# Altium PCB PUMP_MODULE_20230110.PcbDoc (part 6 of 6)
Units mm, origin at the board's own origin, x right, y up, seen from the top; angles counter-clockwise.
Board outline 260.15 x 142.01 mm, 4 copper layers (Top Layer, Mid-Layer 1, Mid-Layer 2, Bottom Layer); 422 components, 240 nets, 1746 pads, 416 vias.
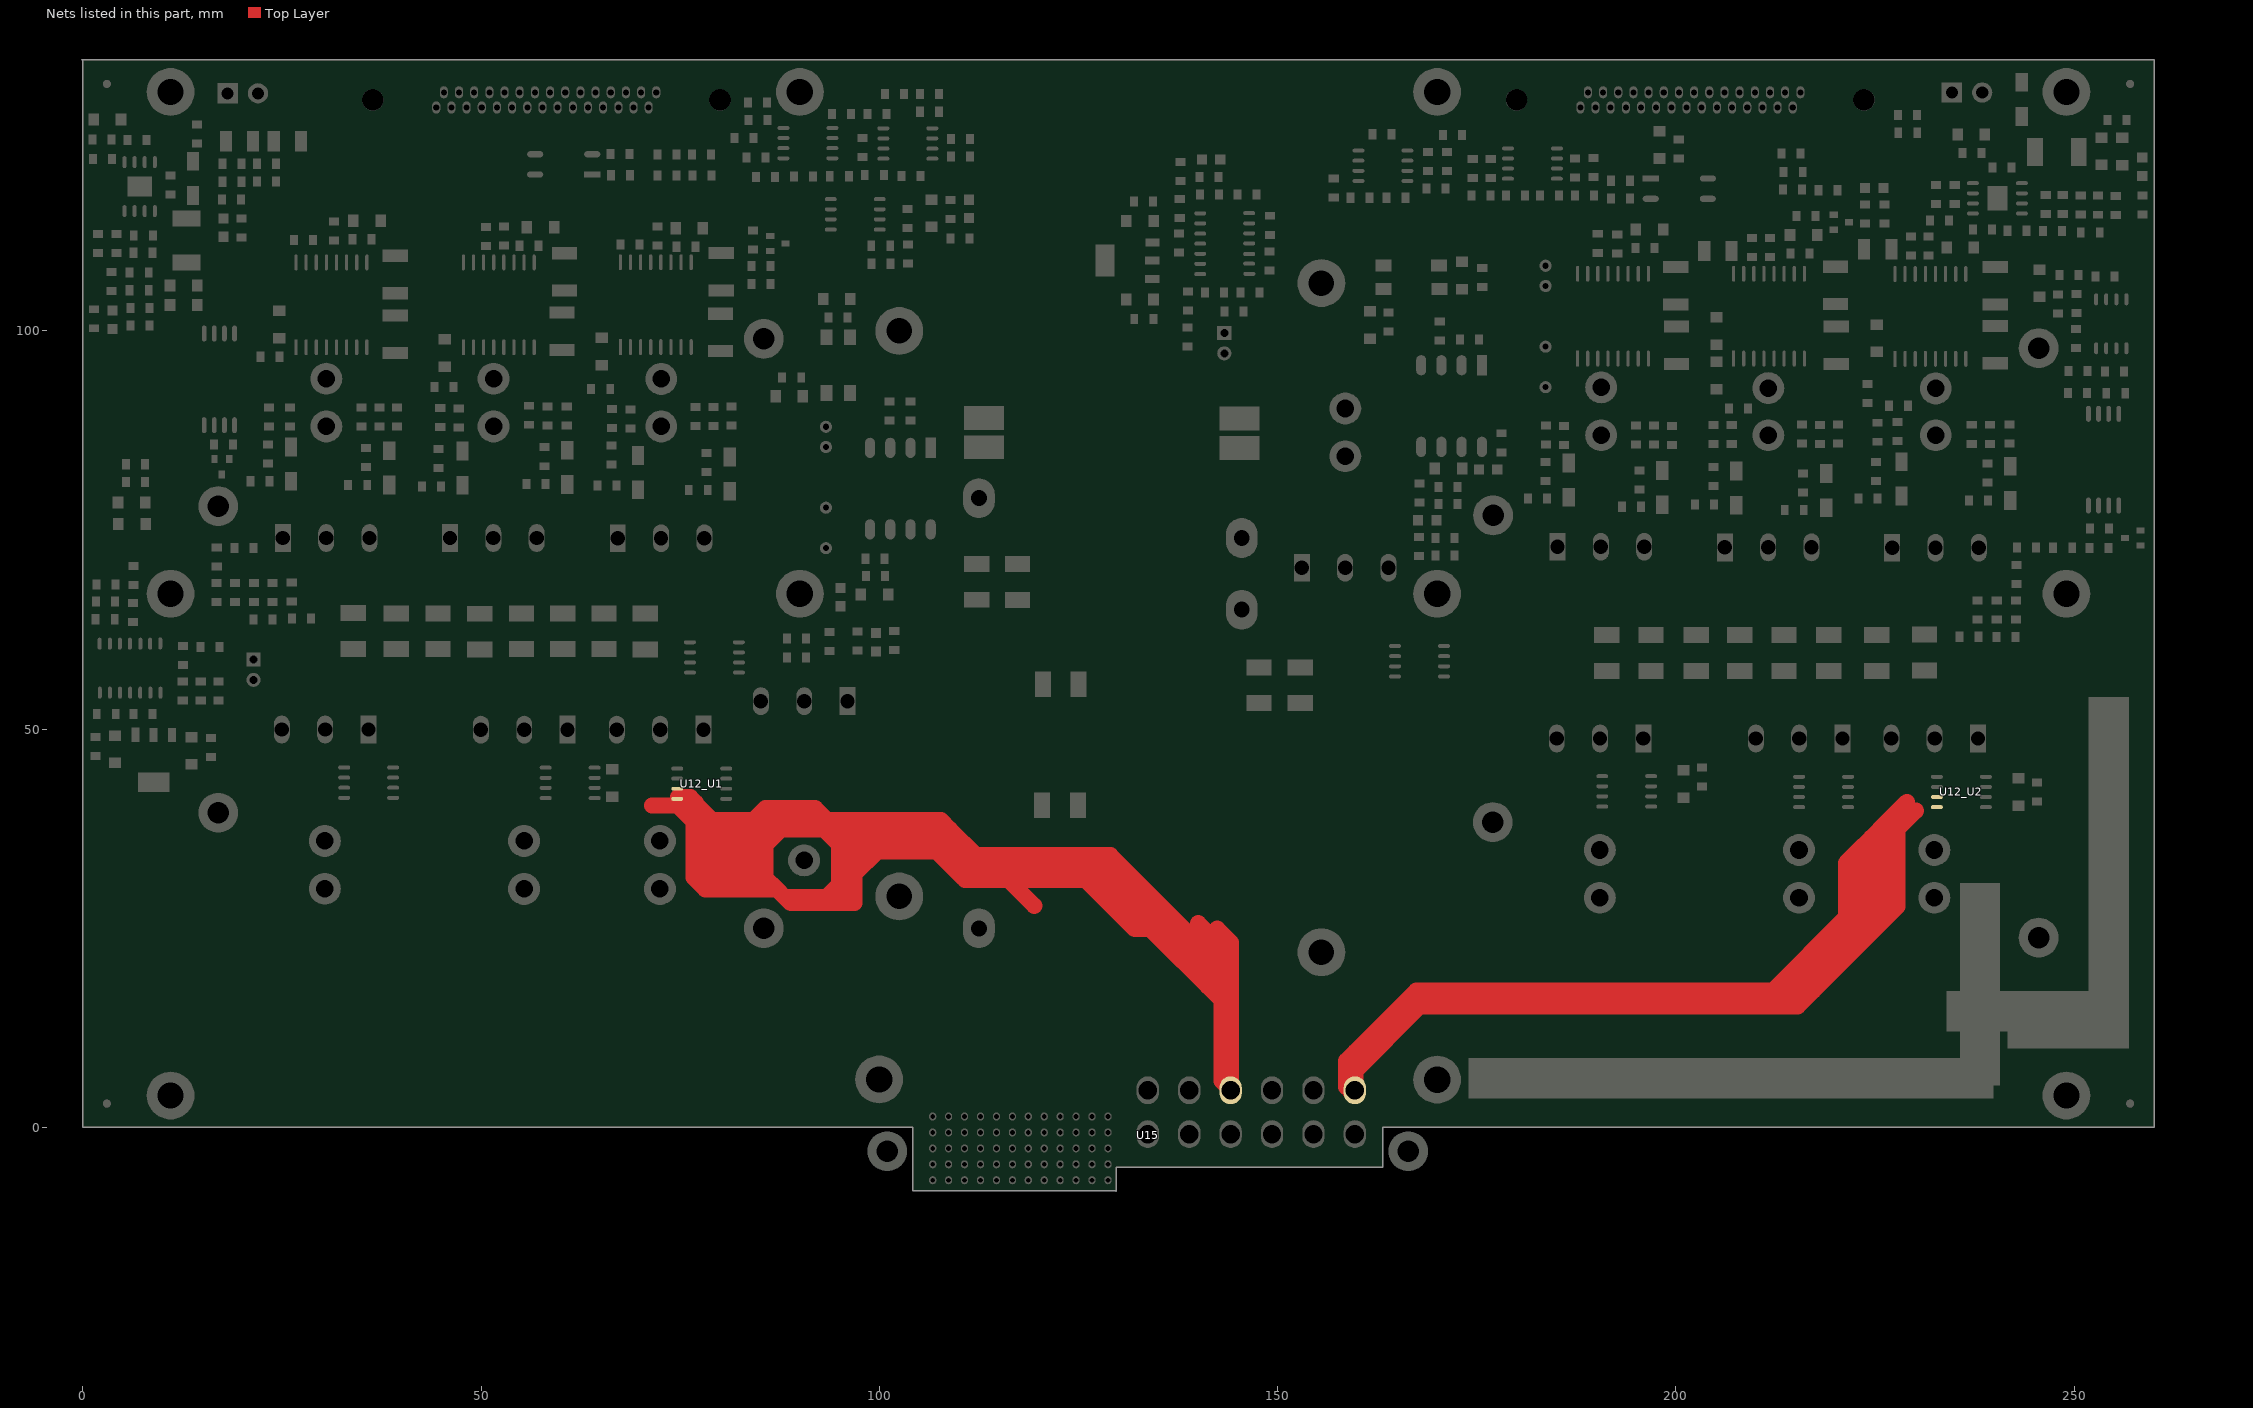
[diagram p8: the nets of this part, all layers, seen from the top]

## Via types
v1: diameter 0.762, hole 0.508, Top Layer to Bottom Layer, 208 vias
v2: diameter 2.032, hole 1.27, Top Layer to Bottom Layer, 78 vias
v3: diameter 1.27, hole 0.762, Top Layer to Bottom Layer, 61 vias
v4: diameter 1.524, hole 1.016, Top Layer to Bottom Layer, 53 vias
v5: diameter 1.27, hole 0.711, Top Layer to Bottom Layer, 16 vias

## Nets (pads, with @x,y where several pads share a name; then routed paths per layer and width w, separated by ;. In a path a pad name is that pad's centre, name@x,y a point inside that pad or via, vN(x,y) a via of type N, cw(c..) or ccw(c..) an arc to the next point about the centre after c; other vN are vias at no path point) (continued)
WW_OUT1: U12_U1.3 U12_U1.4 U15.3 | length 454.5
  Top Layer w2.032: 71.476,40.411 74.701,40.411 76.391,38.722 ; U12_U1.4@74.727,41.478 76.251,41.478 ; 76.632,38.481 77.013,38.1 ; 76.657,37.973 76.657,35.255 ; 78.232,36.881 77.013,38.1 ; 119.456,27.838 116.205,31.09 ; 126.848,34.163 128.054,32.956 ; 140.03,25.629 144.141,21.518 ; 142.418,24.943 144.141,23.219 144.141,21.518 ; 76.251,41.478 76.251,41.326 76.276,41.3 ; 76.251,41.478 76.276,41.453 ; 76.276,41.3 76.962,40.615 ; 76.276,41.3 76.276,41.453 ; 76.276,41.3 76.276,39.497 77.343,38.43 ; 76.276,41.453 76.962,40.767 76.962,40.615 ; 76.657,33.68 76.657,31.394 78.156,29.896 80.442,29.896 ; 76.657,33.68 76.657,35.255 ; 76.657,33.68 77.775,32.563 ; 76.657,35.255 77.597,34.315 84.582,34.315 85.7,35.433 ; 76.962,40.615 77.343,40.234 ; 77.013,38.1 77.343,38.43 ; 77.013,38.1 77.013,35.941 77.521,35.433 85.7,35.433 ; 77.343,38.43 77.343,39.37 ; 77.343,38.43 78.969,36.805 78.969,37.744 ; 77.343,39.37 77.343,40.234 ; 77.343,39.37 78.969,37.744 ; 77.343,40.234 79.019,38.557 84.176,38.557 ; 77.775,32.563 79.273,31.064 ; 77.775,32.563 85.115,32.563 85.7,33.147 ; 78.969,37.744 79.273,37.44 87.706,37.44 ; 79.273,31.064 80.442,29.896 ; 79.273,31.064 79.35,31.14 85.7,31.14 ; 80.442,29.896 84.607,29.896 ; 84.176,38.557 85.7,40.081 90.881,40.081 ; 84.176,38.557 92.405,38.557 ; 84.607,29.896 87.147,29.896 ; 84.607,29.896 85.776,31.064 85.7,31.14 ; 85.7,31.14 85.7,31.344 ; 85.7,31.344 87.147,29.896 ; 85.7,31.344 85.7,33.147 ; 85.7,33.147 85.7,35.433 ; 85.7,35.433 87.706,37.44 ; 87.147,29.896 88.151,28.892 ; 87.706,37.44 93.015,37.44 ; 88.151,28.892 88.875,28.169 95.275,28.169 ; 88.151,28.892 93.332,28.892 94.945,30.505 ; 90.881,40.081 91.948,40.081 93.472,38.557 ; 90.881,40.081 92.405,38.557 ; 92.405,38.557 93.472,38.557 ; 93.015,37.44 94.945,35.509 ; 93.015,37.44 108.864,37.44 ; 93.472,38.557 107.747,38.557 108.864,37.44 ; 94.945,30.505 94.945,35.509 ; 94.945,30.505 94.945,28.499 95.275,28.169 ; 94.945,35.509 99.644,35.509 ; 94.945,35.509 95.771,34.684 97.511,34.684 ; 95.275,28.169 96.876,28.169 96.876,31.775 ; 96.876,31.775 96.876,32.741 ; 96.876,31.775 99.784,34.684 ; 96.876,32.741 96.876,34.049 97.511,34.684 ; 96.876,32.741 98.819,34.684 ; 97.511,34.684 98.819,34.684 ; 98.819,34.684 99.784,34.684 ; 98.819,34.684 99.644,35.509 ; 99.644,35.509 100.571,35.509 101.397,34.684 ; 99.644,35.509 99.746,35.611 106.248,35.611 ; 99.784,34.684 101.397,34.684 ; 101.397,34.684 107.175,34.684 ; 106.248,35.611 108.458,35.611 111.303,32.766 126.162,32.766 ; 106.248,35.611 107.175,34.684 ; 107.175,34.684 110.49,31.369 ; 108.864,37.44 112.141,34.163 124.765,34.163 ; 110.49,31.369 110.769,31.09 116.205,31.09 ; 110.49,31.369 125.603,31.369 125.882,31.09 ; 116.205,31.09 125.882,31.09 ; 124.765,34.163 129.007,34.163 144.141,19.028 ; 124.765,34.163 126.162,32.766 ; 125.882,31.09 132.055,24.917 134.01,24.917 135.077,23.851 ; 126.162,32.766 135.077,23.851 ; 126.162,32.766 127.864,32.766 128.054,32.956 ; 128.054,32.956 136.601,24.409 ; 135.077,23.851 136.042,23.851 136.601,24.409 ; 135.077,23.851 141.224,17.704 ; 136.601,24.409 144.141,16.869 ; 141.224,17.704 142.977,15.951 ; 141.224,17.704 142.977,17.704 ; 142.977,7.518 142.977,15.951 ; 142.977,7.518 U15.3@144.141,6.354 ; 142.977,7.518 142.977,5.827 144.141,4.663 U15.3@144.141,6.354 ; 142.977,15.951 142.977,17.704 ; 142.977,17.704 144.141,16.539 ; U15.3@144.141,6.354 144.141,16.539 ; 144.141,16.539 144.141,16.869 ; 144.141,16.869 144.141,19.028 ; 144.141,19.028 144.141,21.518
WW_OUT2: U12_U2.3 U12_U2.4 U15.6 | length 236.1
  Top Layer w2.032: 229.006,40.869 226.416,38.278 ; 230.124,39.751 227.813,37.44 227.813,27.737 217.246,17.17 ; 159.741,7.087 159.741,9.5 ; 159.741,7.087 159.741,4.663 159.04,4.663 158.623,5.08 158.623,8.382 159.741,9.5 ; 159.741,7.087 167.869,15.215 215.29,15.215 217.246,17.17 ; 159.741,9.5 167.411,17.17 212.141,17.17 ; 212.141,17.17 214.63,17.17 ; 212.141,17.17 221.336,26.365 ; 214.63,17.17 217.246,17.17 ; 214.63,17.17 226.416,28.956 226.416,38.278 ; 221.336,26.365 221.336,33.198 222.847,34.709 ; 221.336,26.365 222.847,27.877 ; 222.847,27.877 222.847,34.709 ; 222.847,27.877 224.511,29.54 224.511,36.373 ; 222.847,34.709 224.511,36.373 ; 224.511,36.373 226.416,38.278
pads on no net: C4.0 P4_U1. P4_U1.9 P4_U1.10 P4_U1.22 P4_U1.24 P4_U1.25 P4_U2. P4_U2.9 P4_U2.10 P4_U2.22 P4_U2.24 P4_U2.25 Q1_U1. Q1_U2. Q2_U1. Q2_U2. Q3_U1. Q3_U2. Q4_U1. Q4_U2. Q5_U1. Q5_U2. Q7_U1. Q7_U2. Q8_U1. Q8_U2. U1_U1.5 U1_U1.6 U1_U1.7 U1_U2.5 U1_U2.6 U1_U2.7 U2_U1.4 U2_U2.4 U5_U1.6 U5_U2.6 U6_U1.4 U6_U1.5 U6_U1.9 U6_U1.10 U6_U1.16 U6_U2.4 U6_U2.5 U6_U2.9 U6_U2.10 U6_U2.16 U7_U1.6 U7_U2.6 U9_U1.4 U9_U1.5 U9_U1.9 U9_U1.10 U9_U1.16 U9_U2.4 U9_U2.5 U9_U2.9 U9_U2.10 U9_U2.16 U10_U1.6 U10_U2.6 U11_U1.4 U11_U1.5 U11_U1.9 U11_U1.10 U11_U1.16 U11_U2.4 U11_U2.5 U11_U2.9 U11_U2.10 U11_U2.16 U12_U1.6 U12_U2.6 U15. U15.8 U15.9 U15.10 U15.11 U15.A1 U15.A2 U15.A3 U15.A4 U15.A5 U15.A6 U15.A7 U15.A8 U15.A9 U15.A10 U15.A11 U15.A12 U15.B1 U15.B2 U15.B3 U15.B4 U15.B5 U15.B6 U15.B7 U15.B8 U15.B9 U15.B10 U15.B11 U15.B12 U15.C1 U15.C2 U15.C3 U15.C4 U15.C5 U15.C6 U15.C7 U15.C8 U15.C9 U15.C10 U15.C11 U15.C12 U15.D1 U15.D2 U15.D3 U15.D4 U15.D5 U15.D6 U15.D7 U15.D8 U15.D9 U15.D10 U15.D11 U15.D12 U15.E1 U15.E2 U15.E3 U15.E4 U15.E5 U15.E6 U15.E7 U15.E8 U15.E9 U15.E10 U15.E11 U15.E12 U17_U1.1 U17_U1.4 U17_U1.6 U17_U2.1 U17_U2.4 U17_U2.6

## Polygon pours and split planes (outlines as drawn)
AGND_U2 on Bottom Layer "Top Layer-No Net" (solid, remove dead copper, pour order 18): 128.448,133.985 127.61,133.147 127.61,101.422 146.558,101.422 150.012,104.877 150.012,107.188 150.012,114.859 149.098,115.773 190.5,115.773 190.729,116.002 190.881,115.849 195.478,115.849 197.637,115.849 197.79,115.697 197.714,115.773 197.714,133.909 175.59,133.909 175.514,133.833 175.438,133.909 174.904,133.909 174.904,126.441 174.447,125.984 174.219,125.755 165.837,125.755 165.837,125.781 164.846,126.771 164.541,127.076 164.541,133.909 127.701,133.909 127.61,134 127.635,133.975 127.635,133.02
AGND_U1 on Bottom Layer "Top Layer-No Net" (solid, remove dead copper, pour order 13): 65.43,133.794 65.481,133.744 65.481,118.377 91.389,118.377 93.523,116.243 93.65,116.116 93.65,112.281 112.166,112.281 112.395,112.509 112.395,133.794 93.802,133.794 93.98,133.617 93.98,126.047 85.852,126.047 85.801,125.997 85.446,126.352 85.446,133.896 65.43,133.896
+5VA_U2 on Mid-Layer 2 "Top Layer-No Net" (solid, remove dead copper, pour order 17): 128.549,133.782 127.711,132.944 127.711,101.219 146.66,101.219 150.114,104.673 150.114,106.985 150.114,114.656 149.2,115.57 190.602,115.57 190.83,115.799 190.983,115.646 195.58,115.646 197.739,115.646 197.891,115.494 197.815,115.57 197.815,133.706 175.692,133.706 175.616,133.629 175.539,133.706 175.006,133.706 175.006,126.238 174.549,125.781 174.32,125.552 165.938,125.552 165.938,125.578 164.948,126.568 164.643,126.873 164.643,133.706 127.802,133.706 127.711,133.797 127.737,133.771 127.737,132.817
+5VA_U1 on Mid-Layer 2 "Top Layer-No Net" (solid, remove dead copper, pour order 12): 65.507,133.909 65.557,133.858 65.557,118.491 91.465,118.491 93.599,116.357 93.726,116.23 93.726,112.395 112.243,112.395 112.471,112.624 112.471,133.909 93.878,133.909 94.056,133.731 94.056,126.162 85.928,126.162 85.877,126.111 85.522,126.467 85.522,134.01 65.507,134.01
AGND_U2 on Top Layer "Top Layer-No Net" (solid, remove dead copper, pour order 16): 128.448,133.883 127.61,133.045 127.61,101.321 146.558,101.321 150.012,104.775 150.012,107.086 150.012,114.757 149.098,115.672 190.5,115.672 190.729,115.9 190.881,115.748 195.478,115.748 197.637,115.748 197.79,115.595 197.714,115.672 197.714,133.807 175.59,133.807 175.514,133.731 175.438,133.807 174.904,133.807 174.904,126.34 174.447,125.882 174.219,125.654 165.837,125.654 165.837,125.679 164.846,126.67 164.541,126.975 164.541,133.807 127.701,133.807 127.61,133.898 127.635,133.873 127.635,132.918
AGND_U1 on Top Layer "Top Layer-No Net" (solid, remove dead copper, pour order 11): 65.507,134.087 65.557,134.036 65.557,118.669 91.465,118.669 93.599,116.535 93.726,116.408 93.726,112.573 112.243,112.573 112.471,112.801 112.471,134.087 93.878,134.087 94.056,133.909 94.056,126.34 85.928,126.34 85.877,126.289 85.522,126.644 85.522,134.188 65.507,134.188
AGND_U2 on Mid-Layer 1 "Top Layer-No Net" (solid, remove dead copper, pour order 15): 128.448,134 127.61,133.162 127.61,101.437 146.558,101.437 150.012,104.892 150.012,107.203 150.012,114.874 149.098,115.788 190.5,115.788 190.729,116.017 190.881,115.864 195.478,115.864 197.637,115.864 197.79,115.712 197.714,115.788 197.714,133.924 175.59,133.924 175.514,133.848 175.438,133.924 174.904,133.924 174.904,126.456 174.447,125.999 174.219,125.77 165.837,125.77 165.837,125.796 164.846,126.786 164.541,127.091 164.541,133.924 127.701,133.924 127.61,134.015 127.635,133.99 127.635,133.035
AGND_U2 on Mid-Layer 1 "Top Layer-No Net" (solid, remove dead copper, pour order 14): 249.276,108.788 249.276,88.621 250.292,87.605 250.317,87.579 256.261,87.579 256.261,106.959 254.864,108.356 254.533,108.687 249.326,108.687
AGND_U1 on Mid-Layer 1 "Top Layer-No Net" (solid, remove dead copper, pour order 10): 65.456,133.909 65.507,133.858 65.507,118.491 91.415,118.491 93.548,116.357 93.675,116.23 93.675,112.395 112.192,112.395 112.42,112.624 112.42,133.909 93.828,133.909 94.005,133.731 94.005,126.162 85.877,126.162 85.827,126.111 85.471,126.467 85.471,134.01 65.456,134.01

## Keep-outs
Keep-Out Layer:
  lines w0.254: 0.023,3 ccw(c3.023,3) 3.023,0 92.475,0 92.475,2.525 104.175,2.525 104.175,0.025 104.175,-7.976 129.675,-7.976 129.675,-4.975 ; 0.025,3 0.025,130.988 cw(c3.025,130.988) 3.025,133.988 ; 3.025,134 257.023,134 ; 104.225,-8.001 129.725,-8.001 129.725,-5 ; 129.667,-4.975 163.175,-4.975 ; 129.718,-5 163.149,-5 163.175,-4.975 ; 176.113,2.525 176.175,2.464 ; 176.149,0 257.023,0 ccw(c257.023,3) 260.023,3 ; 176.175,0.025 176.175,2.525 163.175,2.525 163.175,-4.975 ; 257.023,134.01 cw(c257.023,131.01) 260.023,131.01 260.023,2.972

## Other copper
Top Layer:
  rectangle net PGND: 17.323,2.261 24.587,34.95
  rectangle net PGND: 20.625,20.371 24.587,52.019
  rectangle net PGND: 43.663,48.184 51.054,56.261
  rectangle net PGND: 64.567,48.158 68.351,56.007
  rectangle net PGND: 26.746,53.67 45.136,59.411
  rectangle net WW_OUT1: 117.5,23.876 143.942,33.198
  rectangle net VV_OUT1: 58.75,16.891 75.59,25.806
  rectangle net UU_OUT1: 36.957,2.108 90.627,13.437
  rectangle net UU_OUT1: 33.985,2.032 39.345,16.434
  rectangle net PGND: 176.911,0.406 240.894,11.633
  rectangle net PGND: 42.697,20.142 51.308,30.582
  rectangle net PGND: 174.422,3.759 178.765,10.77
  rectangle net ISO_GND_U2: 165.964,101.219 186.512,103.429
  rectangle net ISO_GND_U2: 149.225,96.266 166.472,100.33
  rectangle net ISO_GND_U2: 142.164,87.478 149.962,94.107
  rectangle net ISO_GND_U1: 42.342,114.656 46.05,123.469
  rectangle net ISO_GND_U1: 110.261,87.706 116.103,96.215
  rectangle net ISO_GND_U1: 98.628,90.322 102.159,96.241
  rectangle net ISO_GND_U1: 98.628,92.507 116.053,96.241
  rectangle net PGND: 253.416,57.404 259.004,72.796
  rectangle net ISO_+15V_U2: 197.561,105.512 204.241,110.693
  rectangle net ISO_+15V_U2: 216.891,106.172 222.936,110.922
  rectangle net NetC13_U2_1: 242.164,118.262 246.075,126.238
  rectangle net ISO_+15V_U2: 229.768,121.615 235.915,131.369
  rectangle net ISO_+15V_U2: 236.855,105.893 241.554,110.592
  rectangle net PGND: 0.762,116.434 8.763,119.659
  rectangle net ISO_+5V_U1: 7.722,99.543 12.217,108.026
  rectangle net NetC13_U1_1: 10.389,113.081 14.757,117.526
  rectangle net NetC13_U1_1: 8.738,113.055 14.757,116.027
  rectangle net ISO_+15V_U1: 77.14,107.29 81.864,112.903
  rectangle net ISO_+15V_U1: 57.277,107.036 61.976,112.268
  rectangle net ISO_+15V_U1: 36.246,107.112 40.996,112.319
  rectangle net NetC36_U1_1: 89.611,87.097 94.183,93.243
  rectangle net HVCC_IN: 108.204,45.161 121.539,66.04
  rectangle net PGND: 146.99,36.195 172.695,45.212
  rectangle net PGND: 133.655,36.246 155.753,53.721
  rectangle net PGND: 123.749,38.608 140.792,81.483
  rectangle net PGND: 110.617,70.663 148.057,86.843
  rectangle net PGND: 236.83,52.146 250.038,54.788
  rectangle net PGND: 236.982,27.559 253.263,36.881
  rectangle net PGND: 235.966,15.697 241.478,30.912
  rectangle net PGND: 249.657,10.414 258.953,31.115
  rectangle net PGND: 233.35,8.738 259.004,19.583
  rectangle net PGND: 248.539,27.559 259.004,58.344
  rectangle net PGND: 227.762,0.432 242.849,18.263
  rectangle net PGND: 189.89,52.172 258.42,58.42
  rectangle net HVCC_U2: 176.962,57.963 182.296,60.731
  rectangle net HVCC_U2: 176.428,59.106 185.623,64.821
  rectangle net PGND: 173.888,9.144 184.226,11.582
  rectangle net HVCC_U2: 175.997,60.528 236.144,68.25
  rectangle net U_OUT_U2: 186.842,42.494 192.075,45.618
  rectangle net UU_OUT2: 186.817,38.227 193.015,41.986
  rectangle net VV_OUT2: 211.76,38.125 217.17,41.885
  rectangle net V_OUT_U2: 210.49,42.393 217.018,45.517
  rectangle net WW_OUT2: 228.625,38.252 234.264,41.935
  rectangle net W_OUT_U2: 229.489,42.393 234.417,45.466
  rectangle net PGND: 42.672,24.181 49.073,56.261
  rectangle net PGND: 32.309,54.788 73.025,61.163
  rectangle net HVCC_IN: 100.508,41.605 121.539,56.337
  rectangle net HVCC_U1: 28.092,63.195 85.674,69.825
  rectangle net HVCC_U1: 80.645,59.284 85.725,66.573
  rectangle net HVCCIN_U1: 80.747,51.689 87.147,58.75
  rectangle net UU_OUT1: 27.051,39.319 34.366,43.129
  rectangle net U_OUT_U1: 26.949,43.459 34.163,46.584
  rectangle net VV_OUT1: 52.172,39.141 58.979,42.951
  rectangle net V_OUT_U1: 52.172,43.205 58.979,46.533
  rectangle net WW_OUT1: 69.367,39.218 75.997,42.951
  rectangle net W_OUT_U1: 69.418,43.51 75.997,46.939
  rectangle net UU_OUT1: 27.051,2.032 39.345,26.391
Mid-Layer 1:
  rectangle net PGND: 177.851,0.711 241.63,10.897
  rectangle net PGND: 174.015,3.581 241.554,11.455
Mid-Layer 2:
  rectangle net PGND: 176.987,0.559 241.503,11.176
  rectangle net PGND: 174.092,3.581 241.554,11.455
Bottom Layer:
  rectangle net AGND_U1: 1.829,34.722 12.929,46.025
  rectangle net AGND_U1: 0.533,34.722 3.48,70.46
  rectangle net AGND_U1: 0.533,70.206 5.715,93.142
  rectangle net HVCC_IN: 144.526,50.65 157.609,62.281
  rectangle net PGND: 203.429,20.142 211.023,50.673
  rectangle net PGND: 223.723,47.117 228.092,68.199
  rectangle net PGND: 222.148,53.797 224.409,79.832
  rectangle net PGND: 62.636,60.096 65.913,69.825
  rectangle net PGND: 42.418,48.514 45.669,69.926
  rectangle net PGND: 17.323,1.702 47.981,26.492
  rectangle net PGND: 61.9,60.173 64.567,81.661
  rectangle net PGND: 40.615,48.514 43.409,81.077
  rectangle net V_OUT_U1: 52.426,47.879 58.166,69.494
  rectangle net PGND: 177.038,0.559 242.722,12.065
  rectangle net PGND: 236.931,27.61 242.672,36.22
  rectangle net PGND: 220.777,23.368 228.854,37.414
  rectangle net ISO_GND_U2: 185.395,101.092 189.484,103.734
  rectangle net ISO_GND_U1: 41.377,108.407 47.168,113.106
  rectangle net ISO_GND_U1: 33.147,105.969 47.142,110.465
  rectangle net ISO_GND_U1: 57.836,105.639 69.215,110.388
  rectangle net ISO_GND_U1: 84.455,102.616 87.147,107.569
  rectangle net ISO_GND_U1: 76.327,104.877 83.109,109.931
  rectangle net ISO_GND_U1: 81.813,104.953 86.893,109.525
  rectangle net ISO_GND_U1: 71.882,105.918 83.058,111.15
  rectangle net ISO_GND_U1: 54.407,105.689 59.207,110.871
  rectangle net ISO_GND_U1: 30.48,104.902 82.677,107.29
  rectangle net PGND: 79.07,81.001 81.407,85.446
  rectangle net PGND: 75.895,81.509 81.432,99.644
  rectangle net PGND: 54.915,83.033 69.088,98.45
  rectangle net PGND: 33.985,81.229 48.108,98.298
  rectangle net PGND: 23.876,82.271 27.407,97.231
  rectangle net PGND: 21.057,80.95 81.432,85.115
  rectangle net PGND: 26.949,97.104 81.382,99.847
  rectangle net PGND: 3.683,101.346 9.042,106.045
  rectangle net PGND: 0.584,102.794 3.785,117.043
  rectangle net PGND: 6.299,105.613 14.707,118.212
  rectangle net PGND: 0.559,96.749 5.944,106.121
  rectangle net PGND: 228.27,80.01 240.97,82.245
  rectangle net PGND: 202.235,78.969 225.374,81.102
  rectangle net PGND: 187.325,79.35 204.064,81.737
  rectangle net PGND: 215.544,82.372 228.549,98.679
  rectangle net PGND: 194.615,81.356 207.797,98.044
  rectangle net PGND: 180.95,79.985 240.513,84.125
  rectangle net PGND: 252.654,111.328 257.175,117.602
  rectangle net PGND: 248.793,120.599 259.055,125.552
  rectangle net PGND: 238.658,113.36 254.102,125.451
  rectangle net PGND: 244.348,70.282 246.38,81.128
  rectangle net PGND: 238.074,80.035 246.38,93.802
  rectangle net PGND: 242.773,54.762 244.983,92.761
  rectangle net PGND: 243.383,54.712 246.431,62.84
  rectangle net PGND: 106.121,33.68 115.926,72.212
  rectangle net PGND: 0.737,116.434 14.63,124.333
  rectangle net PGND: 69.444,4.318 91.77,20.904
  rectangle net PGND: 89.332,10.236 97.942,28.245
  rectangle net PGND: 42.266,1.702 80.62,25.781
  rectangle net PGND: 242.672,27.61 256.464,36.195
  rectangle net PGND: 249.707,8.814 258.877,36.195
  rectangle net PGND: 228.778,8.814 258.877,19.583
  rectangle net PGND: 152.07,27.051 172.644,45.161
  rectangle net PGND: 160.401,9.881 174.828,33.604
  rectangle net PGND: 174.015,3.81 241.427,25.324
  rectangle net W_OUT_U2: 230.124,46.761 235.306,51.537
  rectangle net V_OUT_U2: 213.563,46.965 217.881,52.324
  rectangle net U_OUT_U2: 187.935,47.015 192.634,51.689
  rectangle net PGND: 96.774,33.706 113.335,43.561
  rectangle net PGND: 106.096,70.637 148.438,86.716
  rectangle net U_OUT_U1: 28.194,47.777 32.715,52.705
  rectangle net V_OUT_U1: 53.086,47.981 57.785,52.934
  rectangle net W_OUT_U1: 70.028,47.93 75.006,53.95
  rectangle net HVCC_IN: 119.075,10.389 148.565,67.539
  rectangle net HVCC_IN: 110.49,2.997 129.184,29.261
  rectangle net PGND: 17.323,17.069 24.562,31.877
  rectangle net PGND: 93.828,25.654 97.866,36.5
  rectangle net PGND: 188.798,95.885 241.579,99.035
  rectangle net PGND: 236.245,82.423 241.579,97.307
